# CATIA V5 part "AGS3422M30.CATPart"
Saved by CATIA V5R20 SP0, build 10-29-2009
Part number: AGS3422M30
Definition: NONE
Nomenclature: AGS3422M30
Source: Unknown
Description: AGS3422M30
Bounding box of the stored display mesh (mm): x -39 to 45, y -37 to 37, z -37 to 37
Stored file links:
  C:\Users\Utente\Desktop\IO LAVORO\3D X SITO CF\X SITO\PLASTICA\AGS\AGS3422M30.CATPart
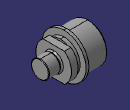
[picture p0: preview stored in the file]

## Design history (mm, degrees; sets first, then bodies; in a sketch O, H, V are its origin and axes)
Body1 "AGS3422M30" (main body)
  Solid1: solid without history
